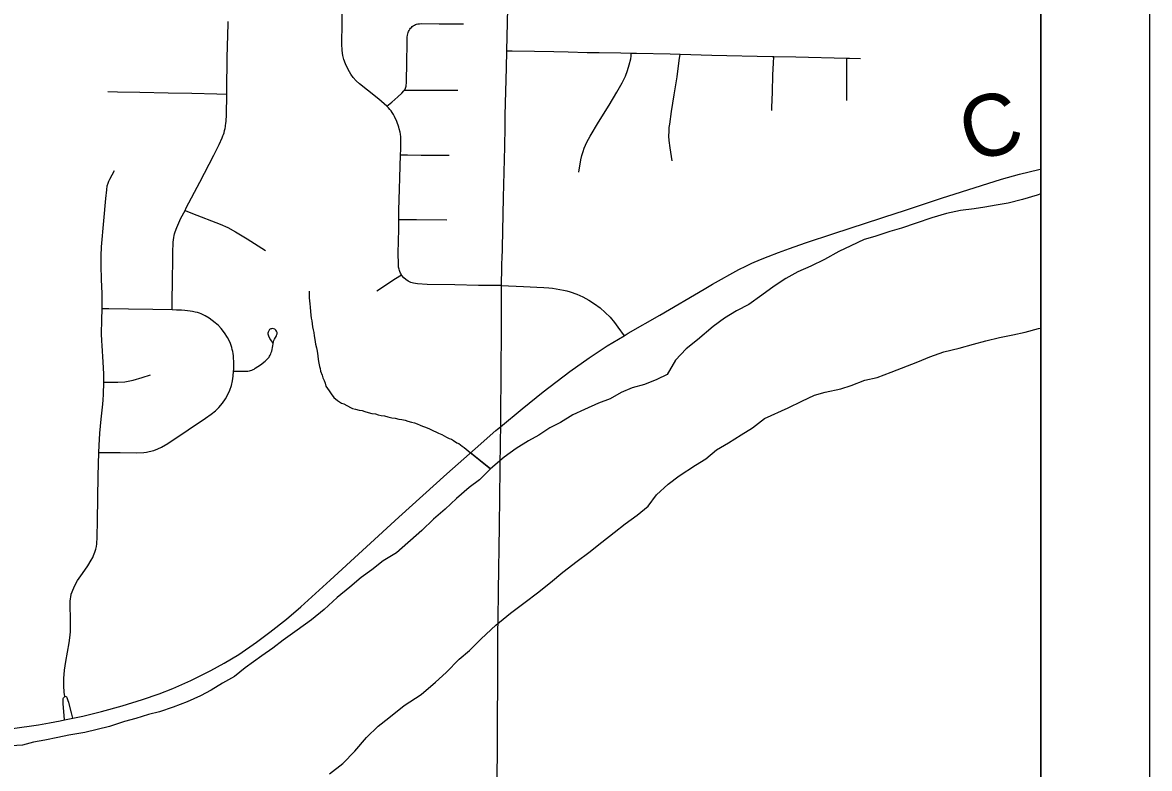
# Model space of a CAD drawing. Extents: x 0 to 34, y 0 to 22.
# Drawn here: x 29.379 to 30.417, y 18.788 to 19.475 of the extents above; entities that cross this region are included whole.
import ezdxf

# ---------------------------------------------------------------- set-up
doc = ezdxf.new("R2010")
doc.units = 0
for name, color, linetype in [('GM_X_City_Street', 7, 'Continuous'), ('GM_X_County_Road', 7, 'Continuous'), ('GM_X_County_Road_Text', 7, 'Continuous'), ('GM_X_Major_River', 7, 'Continuous'), ('GM_X_Minor_River', 7, 'Continuous'), ('GM_X_State_Route', 7, 'Continuous'), ('GM_X_Township_Road', 7, 'Continuous'), ('SH_Data', 7, 'Continuous')]:
    doc.layers.add(name, color=color, linetype=linetype)

msp = doc.modelspace()

# ---------------------------------------------------------------- linework, layer by layer
at = {"layer": 'GM_X_City_Street'}
for points in [[(29.8201, 19.233), (29.7991, 19.2332), (29.7773, 19.2337), (29.7518, 19.2342), (29.7431, 19.2347), (29.741, 19.2349), (29.7393, 19.2352), (29.738, 19.2355), (29.7368, 19.2359), (29.7355, 19.2365), (29.7344, 19.2371), (29.7322, 19.2386), (29.7303, 19.2403), (29.7286, 19.2424), (29.7282, 19.243), (29.7279, 19.2436), (29.7273, 19.2446), (29.7268, 19.2459), (29.7264, 19.2471), (29.726, 19.2482), (29.7258, 19.249), (29.7256, 19.25), (29.7255, 19.2512), (29.7254, 19.2528), (29.7253, 19.2628), (29.7257, 19.2851), (29.7258, 19.294), (29.7259, 19.3026), (29.7265, 19.3218), (29.7268, 19.3324), (29.7274, 19.3535), (29.7275, 19.3585), (29.7277, 19.3659), (29.7277, 19.368), (29.7276, 19.3702), (29.7273, 19.3724), (29.727, 19.3744), (29.7262, 19.3773), (29.7257, 19.3791), (29.7239, 19.3843), (29.7219, 19.3888), (29.7209, 19.3906), (29.7198, 19.3924), (29.7187, 19.3939), (29.7176, 19.3953), (29.7164, 19.3967), (29.7148, 19.3983), (29.7073, 19.4049), (29.6971, 19.413), (29.6897, 19.4188), (29.6865, 19.4218), (29.6839, 19.4246), (29.6816, 19.4277), (29.6791, 19.4321), (29.6766, 19.4372), (29.6751, 19.4414), (29.6742, 19.4451), (29.6736, 19.4495), (29.6734, 19.4558), (29.6737, 19.4747), (29.674, 19.492)], [(29.5171, 19.2106), (29.5173, 19.2177), (29.5176, 19.2384), (29.5178, 19.2569), (29.5179, 19.2662), (29.518, 19.27), (29.518, 19.2717), (29.5182, 19.2731), (29.5188, 19.2775), (29.5191, 19.2793), (29.5194, 19.2807), (29.5199, 19.2825), (29.5215, 19.2866), (29.5253, 19.2952), (29.529, 19.3023), (29.5301, 19.3046), (29.5425, 19.3283), (29.5554, 19.3531), (29.5605, 19.363), (29.5633, 19.3692), (29.5639, 19.3709), (29.5644, 19.3722), (29.5649, 19.3738), (29.5654, 19.3758), (29.5659, 19.3779), (29.5662, 19.3795), (29.5664, 19.3809), (29.5666, 19.3822), (29.5668, 19.3849), (29.5671, 19.39), (29.5674, 19.4095), (29.5674, 19.4131), (29.5679, 19.4429), (29.5687, 19.4746), (29.5687, 19.4764)], [(29.7148, 19.3983), (29.7192, 19.402), (29.7249, 19.4069), (29.7286, 19.4104), (29.7303, 19.4124), (29.7308, 19.4131), (29.7315, 19.4141), (29.7318, 19.415), (29.7322, 19.4159), (29.7324, 19.4169), (29.7325, 19.4178), (29.7328, 19.4194), (29.7329, 19.421), (29.7332, 19.4385), (29.7334, 19.4565), (29.7336, 19.462), (29.7338, 19.4636), (29.7341, 19.465), (29.7344, 19.4661), (29.7348, 19.4672), (29.7352, 19.4681), (29.7359, 19.4692), (29.7365, 19.4701), (29.7373, 19.4709), (29.7381, 19.4717), (29.7391, 19.4724), (29.7401, 19.473), (29.7411, 19.4734), (29.7422, 19.4738), (29.7434, 19.4741), (29.7447, 19.4743), (29.7463, 19.4744), (29.763, 19.4743), (29.7853, 19.4741)], [(29.4579, 19.4117), (29.467, 19.4116), (29.4875, 19.4112), (29.5136, 19.4106), (29.5354, 19.4103), (29.5583, 19.4097), (29.5674, 19.4095)], [(29.7308, 19.4131), (29.7388, 19.4131), (29.7669, 19.413), (29.7802, 19.413)], [(29.7274, 19.3535), (29.7338, 19.3534), (29.7462, 19.3532), (29.7669, 19.3532), (29.7722, 19.3531)], [(29.529, 19.3023), (29.536, 19.2995), (29.5615, 19.2896), (29.5683, 19.2865), (29.5755, 19.2827), (29.5862, 19.2762), (29.5928, 19.2718), (29.603, 19.2653)], [(29.7258, 19.294), (29.7329, 19.294), (29.7422, 19.294), (29.77, 19.2936)], [(29.7054, 19.2283), (29.7227, 19.2395), (29.7282, 19.243)], [(29.8201, 19.233), (29.8404, 19.2322), (29.8527, 19.2316), (29.8591, 19.2313), (29.864, 19.231), (29.8673, 19.2307), (29.8707, 19.2302), (29.8775, 19.2289), (29.8804, 19.2282), (29.8836, 19.2273), (29.8895, 19.2252), (29.8952, 19.2226), (29.9007, 19.2196), (29.906, 19.2162), (29.911, 19.2125), (29.9158, 19.2084), (29.9202, 19.204), (29.9244, 19.199), (29.9275, 19.1949), (29.9332, 19.1869)], [(29.4497, 19.0793), (29.4558, 19.0793), (29.4692, 19.0792), (29.4847, 19.079), (29.491, 19.0793), (29.4936, 19.0796), (29.4961, 19.0801), (29.5003, 19.0812), (29.5039, 19.0826), (29.5073, 19.0842), (29.5133, 19.0877), (29.532, 19.1001), (29.5479, 19.1109), (29.5531, 19.1145), (29.557, 19.1177), (29.5601, 19.1208), (29.5634, 19.1247), (29.5662, 19.1289), (29.5684, 19.1328), (29.5702, 19.1368), (29.5717, 19.141), (29.5727, 19.1453), (29.5731, 19.1476), (29.5734, 19.1497), (29.5737, 19.1541), (29.5738, 19.1559), (29.5738, 19.1635), (29.5737, 19.1659), (29.5735, 19.1685), (29.5732, 19.1704), (29.5729, 19.1723), (29.5725, 19.1741), (29.5721, 19.176), (29.5715, 19.1778), (29.5708, 19.1798), (29.5701, 19.1813), (29.5681, 19.1853), (29.5654, 19.1896), (29.5624, 19.1936), (29.5598, 19.1964), (29.5569, 19.1989), (29.5513, 19.203), (29.5475, 19.2053), (29.544, 19.2069), (29.5422, 19.2076), (29.5404, 19.2082), (29.5382, 19.2087), (29.536, 19.2091), (29.5337, 19.2096), (29.5313, 19.2099), (29.5287, 19.2101), (29.5259, 19.2103), (29.5212, 19.2105), (29.5171, 19.2106), (29.4994, 19.2109), (29.4769, 19.2112), (29.4589, 19.2116), (29.4527, 19.2118)], [(29.5737, 19.1541), (29.5786, 19.1541), (29.5837, 19.1541), (29.5868, 19.1542), (29.5882, 19.1545), (29.5893, 19.1548), (29.5905, 19.1552), (29.5916, 19.1557), (29.5927, 19.1562), (29.5937, 19.1569), (29.5984, 19.16), (29.6028, 19.1635), (29.6047, 19.1652), (29.6055, 19.1661), (29.6063, 19.1671), (29.6069, 19.1681), (29.6075, 19.1691), (29.608, 19.1703), (29.6084, 19.1715), (29.6088, 19.1727), (29.6097, 19.1777), (29.6104, 19.1813), (29.6108, 19.1824), (29.6113, 19.1836), (29.6132, 19.1868), (29.6136, 19.188), (29.6137, 19.1886), (29.6137, 19.1899), (29.6133, 19.191), (29.6126, 19.1921), (29.6116, 19.1929), (29.6105, 19.1933), (29.6093, 19.1934), (29.6086, 19.1933), (29.608, 19.1932), (29.6074, 19.1929), (29.6069, 19.1925), (29.6064, 19.1921), (29.606, 19.1915), (29.6057, 19.1909), (29.6055, 19.1903), (29.6053, 19.1892), (29.6053, 19.1885), (29.6055, 19.1877), (29.6058, 19.1867), (29.6064, 19.1854), (29.6077, 19.1831), (29.6097, 19.18)], [(29.4544, 19.144), (29.4616, 19.144), (29.4673, 19.144), (29.4735, 19.1444), (29.4782, 19.1452), (29.4812, 19.1459), (29.4895, 19.1485), (29.4972, 19.1509)]]:
    msp.add_lwpolyline(points, dxfattribs=at)
at = {"layer": 'GM_X_County_Road'}
msp.add_line((29.4141, 18.8323), (29.418, 18.8331), dxfattribs=at)
for points in [[(30.1846, 19.3002), (30.1893, 19.3017), (30.2253, 19.3137), (30.2804, 19.3312), (30.2972, 19.3358), (30.3148, 19.34), (30.3167, 19.3404)], [(30.0144, 19.2345), (30.0388, 19.248), (30.0452, 19.2511), (30.0506, 19.2536), (30.0588, 19.2571), (30.0656, 19.2599), (30.0752, 19.2635), (30.0855, 19.2672), (30.1002, 19.2723), (30.1261, 19.2811), (30.1846, 19.3002)], [(29.9332, 19.1869), (29.9368, 19.1891), (29.9659, 19.2058), (30.0067, 19.2297), (30.0144, 19.2345)], [(29.8152, 19.0995), (29.8167, 19.1008), (29.8193, 19.1031), (29.8392, 19.1195), (29.8585, 19.1351), (29.8832, 19.154), (29.901, 19.1666), (29.9176, 19.1775), (29.9332, 19.1869)], [(29.418, 18.8331), (29.4258, 18.8346), (29.435, 18.8365), (29.4522, 18.8408), (29.471, 18.846), (29.49, 18.8518), (29.5052, 18.8571), (29.5179, 18.8621), (29.5344, 18.8693), (29.5527, 18.8785), (29.5651, 18.8854), (29.5784, 18.8934), (29.5947, 18.9047), (29.6072, 18.9139), (29.6223, 18.9258), (29.6355, 18.9371), (29.6626, 18.9618), (29.7257, 19.0198), (29.7701, 19.0597), (29.7961, 19.0828), (29.8152, 19.0995)], [(29.1402, 18.8311), (29.1513, 18.83), (29.1916, 18.8268), (29.2158, 18.8252), (29.2592, 18.8228), (29.2909, 18.8217), (29.3083, 18.8215), (29.3337, 18.8221), (29.3485, 18.8231), (29.3702, 18.8252), (29.3941, 18.8285), (29.4042, 18.8304), (29.4141, 18.8323)]]:
    msp.add_lwpolyline(points, dxfattribs=at)
at = {"layer": 'GM_X_Major_River'}
for points in [[(30.3167, 19.3175), (30.3133, 19.3162), (30.2999, 19.3124), (30.2866, 19.309), (30.2755, 19.307), (30.2652, 19.3053), (30.2553, 19.3037), (30.2428, 19.3021), (30.2298, 19.2994), (30.2165, 19.2956), (30.2019, 19.2907), (30.1885, 19.2861), (30.1778, 19.2829), (30.164, 19.2784), (30.1541, 19.2756), (30.1418, 19.2698), (30.1307, 19.2644), (30.1176, 19.2572), (30.1049, 19.251), (30.093, 19.2457), (30.0819, 19.2395), (30.0711, 19.2326), (30.0598, 19.2241), (30.0479, 19.2157), (30.0367, 19.2099)], [(30.0367, 19.2099), (30.0255, 19.203), (30.0151, 19.1953), (30.0007, 19.1831), (29.9903, 19.1747), (29.9805, 19.1643), (29.9729, 19.1512), (29.9633, 19.1465), (29.9518, 19.1419), (29.9404, 19.1388), (29.9304, 19.1345), (29.9204, 19.1287), (29.9097, 19.1248), (29.8966, 19.119), (29.8859, 19.114), (29.8747, 19.1071), (29.8647, 19.102), (29.8547, 19.0954), (29.845, 19.09), (29.8339, 19.0831), (29.8227, 19.075), (29.8102, 19.0643), (29.8001, 19.0543), (29.7904, 19.047), (29.7788, 19.037), (29.7683, 19.0271), (29.7578, 19.0178), (29.7469, 19.0075), (29.7236, 18.9868), (29.7113, 18.9796), (29.7008, 18.9711), (29.6911, 18.9641), (29.6807, 18.9553), (29.669, 18.9457), (29.657, 18.9347), (29.6453, 18.9251), (29.6322, 18.9156), (29.6194, 18.9064), (29.6098, 18.899), (29.5997, 18.8921), (29.5843, 18.8811), (29.5746, 18.873), (29.5634, 18.8668), (29.553, 18.8603), (29.5434, 18.8552), (29.5311, 18.8498), (29.5181, 18.8449), (29.5054, 18.8406), (29.4955, 18.8379), (29.4837, 18.8344), (29.4734, 18.8316), (29.4596, 18.827), (29.4367, 18.8215), (29.4222, 18.8189), (29.4119, 18.8169), (29.4001, 18.8145), (29.3894, 18.8125), (29.3795, 18.8097), (29.3689, 18.8092)], [(29.9988, 19.0678), (30.0084, 19.0736), (30.0181, 19.0817), (30.0293, 19.0882), (30.0408, 19.0955), (30.0512, 19.1021), (30.0625, 19.1105), (30.084, 19.1206), (30.0966, 19.1267), (30.1085, 19.1321), (30.1181, 19.1349), (30.1326, 19.1379), (30.1421, 19.1411), (30.1548, 19.1461), (30.1662, 19.1484), (30.1789, 19.1534), (30.2034, 19.1627), (30.2145, 19.1673), (30.2275, 19.1719), (30.2416, 19.1753), (30.2546, 19.1792), (30.2661, 19.1823), (30.2787, 19.1854), (30.2909, 19.1877), (30.3023, 19.1901), (30.3145, 19.1936), (30.3167, 19.194)], [(29.662, 18.7834), (29.6744, 18.7929), (29.6853, 18.8041), (29.6959, 18.8167), (29.7068, 18.8274), (29.7165, 18.8348), (29.7308, 18.8462), (29.7462, 18.8564), (29.7594, 18.8678), (29.7695, 18.8767), (29.7812, 18.8889), (29.7909, 18.897), (29.8015, 18.9077), (29.8151, 18.9203), (29.8286, 18.9313), (29.8422, 18.9416), (29.8534, 18.95), (29.8654, 18.9596), (29.8767, 18.9692), (29.8898, 18.9791), (29.9007, 18.9872), (29.9127, 18.9967), (29.9239, 19.0055), (29.934, 19.0136), (29.9452, 19.0217), (29.9553, 19.0298), (29.9631, 19.0402), (29.9736, 19.0502), (29.9837, 19.0579), (29.9988, 19.0678)]]:
    msp.add_lwpolyline(points, dxfattribs=at)
at = {"layer": 'GM_X_Minor_River'}
msp.add_lwpolyline([(29.6434, 19.228), (29.6434, 19.2276), (29.6432, 19.2219), (29.6435, 19.2189), (29.6438, 19.2162), (29.6441, 19.2131), (29.6444, 19.2093), (29.6447, 19.2059), (29.645, 19.2032), (29.6456, 19.2006), (29.6459, 19.1979), (29.6462, 19.1952), (29.6469, 19.1922), (29.6476, 19.1899), (29.6479, 19.1868), (29.6486, 19.1834), (29.6492, 19.1792), (29.6499, 19.1757), (29.6505, 19.1727), (29.6512, 19.1685), (29.6514, 19.165), (29.6521, 19.1616), (29.6528, 19.1585), (29.6535, 19.1566), (29.6538, 19.1543), (29.6552, 19.1505), (29.6559, 19.1482), (29.657, 19.1455), (29.658, 19.1432), (29.6587, 19.1405), (29.6602, 19.1382), (29.6616, 19.1362), (29.6634, 19.1335), (29.666, 19.13), (29.6693, 19.1273), (29.6712, 19.1261), (29.6731, 19.1249), (29.6753, 19.124), (29.6813, 19.1208), (29.6832, 19.12), (29.6858, 19.1192), (29.6892, 19.1183), (29.6919, 19.1179), (29.6945, 19.117), (29.6975, 19.1162), (29.7009, 19.1153), (29.7043, 19.1148), (29.7069, 19.114), (29.7096, 19.1135), (29.7126, 19.1131), (29.7156, 19.1122), (29.7194, 19.1114), (29.7224, 19.1109), (29.7258, 19.11), (29.7285, 19.1096), (29.7315, 19.1091), (29.7341, 19.1083), (29.7375, 19.1074), (29.7402, 19.1066), (29.7428, 19.1057), (29.7454, 19.1045), (29.7477, 19.1037), (29.7495, 19.1029), (29.7518, 19.1021), (29.7541, 19.1012), (29.7578, 19.0992), (29.76, 19.0984), (29.7623, 19.0972), (29.7653, 19.096), (29.7675, 19.0948), (29.7698, 19.0936), (29.772, 19.0923), (29.7743, 19.0915), (29.7761, 19.0903), (29.7791, 19.0883), (29.781, 19.0875), (29.784, 19.0852), (29.7858, 19.084), (29.7877, 19.0824), (29.7895, 19.0808), (29.8101, 19.0642), (29.7921, 19.0788), (29.7918, 19.0789)], dxfattribs=at)
at = {"layer": 'GM_X_State_Route'}
for points in [[(29.8346, 19.8657), (29.8343, 19.8532), (29.8333, 19.8233), (29.8317, 19.7506), (29.8297, 19.6617), (29.8285, 19.6008), (29.8276, 19.5688), (29.8274, 19.5635), (29.8269, 19.5373), (29.8264, 19.515), (29.8249, 19.4494), (29.8245, 19.4336), (29.8235, 19.3901), (29.8233, 19.3794)], [(29.8233, 19.3794), (29.823, 19.3609), (29.8219, 19.3143), (29.8208, 19.2677), (29.8205, 19.257), (29.8204, 19.2546)], [(29.8204, 19.2546), (29.8203, 19.25), (29.8201, 19.233), (29.82, 19.1977), (29.8197, 19.1476), (29.8195, 19.1179)], [(29.8195, 19.1179), (29.8193, 19.1031), (29.8192, 19.09), (29.8185, 19.0386), (29.8181, 19.0115), (29.8173, 18.9518), (29.8169, 18.925)], [(29.8169, 18.925), (29.8167, 18.9141), (29.8165, 18.8688), (29.8164, 18.8327), (29.8159, 18.7525), (29.8156, 18.7251), (29.8146, 18.6847), (29.8137, 18.6586), (29.8099, 18.5785), (29.8074, 18.519), (29.804, 18.4412), (29.8003, 18.3595)]]:
    msp.add_lwpolyline(points, dxfattribs=at)
at = {"layer": 'GM_X_Township_Road'}
for points in [[(28.8021, 16.3696), (29.7483, 16.3505), (30.2361, 16.3375), (30.2681, 16.3359), (30.2735, 16.3357), (30.315, 16.335), (30.3167, 16.335), (30.3167, 20.9), (28.9104, 20.9)], [(29.8249, 19.4494), (29.8301, 19.4493), (29.8506, 19.4491), (29.8686, 19.4486), (29.8817, 19.4484), (29.899, 19.4479), (29.9102, 19.4478), (29.9301, 19.4474), (29.9397, 19.4471)], [(29.8916, 19.3376), (29.8934, 19.3488), (29.8943, 19.353), (29.8954, 19.3566), (29.8964, 19.3595), (29.8989, 19.3652), (29.9018, 19.3707), (29.9095, 19.3835), (29.9193, 19.3994), (29.9264, 19.4111), (29.9313, 19.4197), (29.9343, 19.4259), (29.9364, 19.4311), (29.9379, 19.4363), (29.9392, 19.4418), (29.9395, 19.4443), (29.9397, 19.4471)], [(29.9397, 19.4471), (29.9444, 19.447), (29.9755, 19.4464), (29.9847, 19.4462)], [(29.9773, 19.348), (29.9755, 19.3598), (29.9747, 19.3667), (29.9744, 19.3708), (29.9745, 19.3754), (29.9747, 19.3787), (29.9752, 19.3816), (29.9769, 19.3933), (29.9792, 19.4087), (29.9819, 19.4254), (29.9839, 19.4404), (29.9847, 19.4462)], [(29.9847, 19.4462), (30.014, 19.4454), (30.0694, 19.4442), (30.0708, 19.4442)], [(30.0691, 19.3942), (30.0692, 19.397), (30.0696, 19.4111), (30.0701, 19.4271), (30.0705, 19.4378), (30.0708, 19.4442)], [(30.0708, 19.4442), (30.0911, 19.4437), (30.138, 19.4426)], [(30.1382, 19.4034), (30.1382, 19.4075), (30.1382, 19.4226), (30.138, 19.4376), (30.138, 19.4426)], [(30.138, 19.4426), (30.1405, 19.4425), (30.1508, 19.4422)], [(29.4527, 19.2118), (29.4527, 19.2158), (29.4526, 19.2257), (29.4521, 19.2388), (29.4517, 19.2517), (29.4517, 19.2605), (29.4521, 19.2687), (29.4543, 19.2928), (29.4561, 19.3133), (29.457, 19.3213), (29.4575, 19.3251), (29.4582, 19.3275), (29.4589, 19.3294), (29.4598, 19.3312), (29.4641, 19.339)], [(29.4544, 19.144), (29.4544, 19.1451), (29.4543, 19.1519), (29.4537, 19.1624), (29.4526, 19.1779), (29.4524, 19.1823), (29.4522, 19.1885), (29.4524, 19.2016), (29.4527, 19.2118)], [(29.4497, 19.0793), (29.4499, 19.0857), (29.4506, 19.0971), (29.4519, 19.1101), (29.4534, 19.1237), (29.4538, 19.1277), (29.454, 19.1327), (29.4544, 19.144)], [(29.4236, 18.9448), (29.4238, 18.946), (29.4243, 18.9487), (29.425, 18.9509), (29.4273, 18.9562), (29.4301, 18.9614), (29.4345, 18.9679), (29.4396, 18.975), (29.4427, 18.9802), (29.4441, 18.9827), (29.4449, 18.9846), (29.4461, 18.9876), (29.447, 18.9903), (29.4475, 18.9928), (29.4478, 18.9953), (29.4481, 19.0013), (29.4485, 19.0168), (29.4491, 19.0578), (29.4497, 19.0793)], [(29.4183, 18.8545), (29.4179, 18.8586), (29.4175, 18.8643), (29.4176, 18.8712), (29.4181, 18.8787), (29.4192, 18.8867), (29.4208, 18.8953), (29.4224, 18.9039), (29.423, 18.9087), (29.4235, 18.9142), (29.4237, 18.9192), (29.4236, 18.9266), (29.4232, 18.9378), (29.4233, 18.9422), (29.4236, 18.9448)], [(29.418, 18.8331), (29.4169, 18.8482), (29.4168, 18.8501), (29.4168, 18.851), (29.4169, 18.852), (29.417, 18.8528), (29.4172, 18.8534), (29.4183, 18.8545)], [(29.4258, 18.8346), (29.4245, 18.8395), (29.422, 18.8491), (29.4215, 18.8507), (29.4212, 18.8516), (29.4209, 18.8525), (29.4205, 18.8532), (29.4201, 18.8539), (29.4195, 18.8543), (29.4183, 18.8545)]]:
    msp.add_lwpolyline(points, dxfattribs=at)
at = {"layer": 'SH_Data'}
for points in [[(23.4167, 21), (30.4167, 21), (30.4167, 14), (23.4167, 14)], [(23.5167, 20.9), (30.3167, 20.9), (30.3167, 14.1), (23.5167, 14.1)]]:
    msp.add_lwpolyline(points, close=True, dxfattribs=at)

# ---------------------------------------------------------------- texts
at = {"layer": 'GM_X_County_Road_Text'}
msp.add_text('C', height=0.0568, rotation=16.2215, dxfattribs=at).set_placement((30.2517, 19.3457))

doc.saveas('drawing.dxf')
